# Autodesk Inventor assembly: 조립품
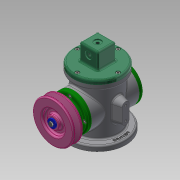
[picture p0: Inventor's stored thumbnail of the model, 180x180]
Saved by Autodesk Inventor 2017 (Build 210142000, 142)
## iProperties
Part Number: 조립품
Material: 일반
Document SubType Name: Assembly
Designer: MRC
Author: MRC
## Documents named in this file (18)
- C:\Users\MRC\Desktop\730206V1004\조립품.iam
- C:\Users\MRC\Desktop\730206V1004\본체.ipt
- C:\Users\MRC\Desktop\730206V1004\E-링.ipt
- C:\Users\MRC\Desktop\730206V1004\V-벨트풀리.ipt
- C:\Users\MRC\Desktop\730206V1004\덮개.ipt
- C:\Users\MRC\Desktop\730206V1004\뒤커버.ipt
- C:\Users\MRC\Desktop\730206V1004\링크.ipt
- C:\Users\MRC\Desktop\730206V1004\베어링 17 x 40 x 12.ipt
- C:\Users\MRC\Desktop\730206V1004\볼트 M4 x 8.ipt
- C:\Users\MRC\Desktop\730206V1004\볼트 M4 x 10.ipt
- C:\Users\MRC\Desktop\730206V1004\슬라이더.ipt
- C:\Users\MRC\Desktop\730206V1004\앞커버.ipt
- C:\Users\MRC\Desktop\730206V1004\오일 실 17 30 8.ipt
- C:\Users\MRC\Desktop\730206V1004\와셔 4x16.ipt
- C:\Users\MRC\Desktop\730206V1004\클레비스 핀 6 x 22.ipt
- 클레비스 핀 6 x 22.ipt
- C:\Users\MRC\Desktop\730206V1004\키 4 x 4 x 12.ipt
- C:\Users\MRC\Desktop\730206V1004\편심축.ipt
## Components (2 placed, 2 different names)
1. E-링:1
2. V-벨트풀리:1
